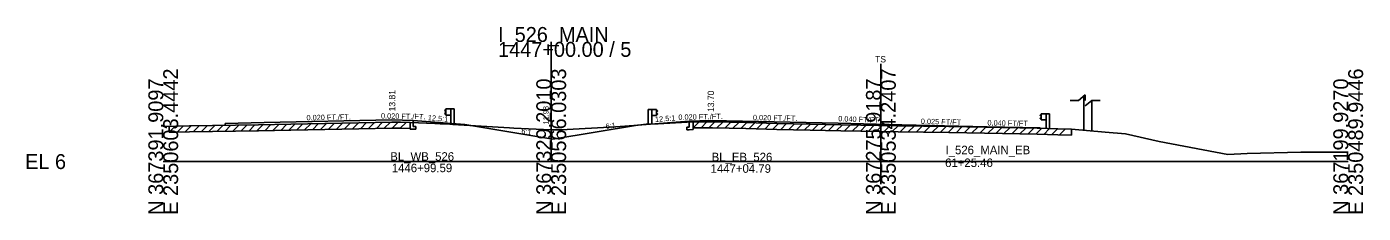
# Model space of a CAD drawing. Extents: x -170 to 2527928, y -10 to 1619750.
# Drawn here: x 4974.3 to 5225.9, y 7990.3 to 8025.3 of the extents above; entities that cross this region are included whole.
import ezdxf

# ---------------------------------------------------------------- set-up
doc = ezdxf.new("R2010")
doc.units = 0
for name, color, linetype in [('Default', 7, 'Continuous'), ('RD_GPK_XS_Cell', 7, 'Continuous'), ('RD_PD_NOISE-WALL-GM', 7, 'Continuous'), ('RD_XS_Base', 7, 'Continuous'), ('RD_XS_EarthShd', 7, 'Continuous'), ('RD_XS_ExGround', 7, 'Continuous'), ('RD_XS_ExPaveRet', 7, 'Continuous'), ('RD_XS_GR', 7, 'Continuous'), ('RD_XS_MatchLine', 7, 'Continuous'), ('RD_XS_Pave', 7, 'Continuous'), ('RD_XS_PaveShd', 7, 'Continuous'), ('RD_XS_TieSlope', 7, 'Continuous'), ('RD_XS_TX_Elev_EX', 7, 'Continuous'), ('RD_XS_TX_Slope', 7, 'Continuous'), ('RD_XS_TX_Station', 7, 'Continuous')]:
    doc.layers.add(name, color=color, linetype=linetype)

msp = doc.modelspace()

# ---------------------------------------------------------------- linework, layer by layer
at = {"layer": 'Default'}
for p, q in [((5173.53, 8012.52), (5172.28, 8011.5)), ((5173.53, 8011.5), (5173.53, 8012.52)), ((5172.28, 8011.5), (5170.7, 8011.5)), ((5174.78, 8011.5), (5173.53, 8010.47)), ((5176.37, 8011.5), (5174.78, 8011.5))]:
    msp.add_line(p, q, dxfattribs=at)
at = {"layer": 'RD_GPK_XS_Cell'}
for p, q in [((5073.02, 8000), (5073.02, 8022.47)), ((5000, 8000), (5073.02, 8000)), ((5073.02, 8000), (5135.07, 8000)), ((5135.07, 8000), (5223.03, 8000))]:
    msp.add_line(p, q, dxfattribs=at)
at = {"layer": 'RD_PD_NOISE-WALL-GM'}
for p, q in [((5173.27, 8005.89), (5173.27, 8012.31)), ((5174.77, 8005.75), (5174.77, 8011.5))]:
    msp.add_line(p, q, dxfattribs=at)
at = {"layer": 'RD_XS_Base'}
for p, q in [((5046.45, 8006.1), (5046.45, 8007.34)), ((5047.02, 8006.59), (5047.02, 8007.73)), ((5099.02, 8006.48), (5099.02, 8007.62)), ((5099.72, 8006), (5099.72, 8007.49)), ((5046.45, 8006.1), (5047.52, 8006.08)), ((5047.52, 8006.58), (5047.02, 8006.59)), ((5047.52, 8006.08), (5047.52, 8006.58)), ((5098.52, 8006.47), (5099.02, 8006.48)), ((5098.52, 8005.97), (5098.52, 8006.47)), ((5099.02, 8005.98), (5098.52, 8005.97)), ((5099.02, 8005.98), (5099.72, 8006)), ((5165.08, 8006.25), (5165.08, 8006.32))]:
    msp.add_line(p, q, dxfattribs=at)
at = {"layer": 'RD_XS_EarthShd'}
for p, q in [((5047.02, 8007.73), (5056.77, 8006.95)), ((5099.02, 8007.62), (5089.27, 8006.84))]:
    msp.add_line(p, q, dxfattribs=at)
at = {"layer": 'RD_XS_ExGround'}
msp.add_lwpolyline([(5000, 8006.59), (5002.37, 8006.66), (5004.93, 8006.7), (5017.94, 8006.89), (5024.04, 8007.03), (5030.44, 8007.17), (5036.84, 8007.3), (5043.05, 8007.41), (5044.65, 8007.38), (5046.45, 8007.34), (5051.12, 8007.18), (5051.81, 8007.15), (5052.14, 8007.11), (5052.55, 8007.1), (5053.36, 8007.07), (5054.52, 8006.98), (5065.18, 8006.33), (5065.96, 8006.28), (5072.94, 8005.99), (5073.87, 8005.94), (5074.88, 8005.99), (5085.13, 8006.5), (5085.16, 8006.5), (5089.39, 8006.87), (5090.89, 8007), (5093.14, 8007.12), (5099.72, 8007.49), (5100.47, 8007.48), (5103.41, 8007.47), (5109.66, 8007.32), (5115.52, 8007.18), (5121.75, 8007.04), (5127.53, 8006.92), (5135.07, 8006.79), (5138.31, 8006.74), (5147.86, 8006.57), (5157.96, 8006.38), (5164.47, 8006.27), (5168.37, 8006.17), (5170.92, 8006.1), (5177.31, 8005.52), (5181.09, 8005.22), (5187.42, 8003.78), (5200.37, 8001.35), (5204.01, 8001.49), (5214.1, 8001.79), (5223.03, 8001.75)], dxfattribs=at)
at = {"layer": 'RD_XS_ExPaveRet'}
for p, q in [((5028.11, 8005.99), (5029.25, 8007.14)), ((5029.61, 8006.03), (5030.75, 8007.17)), ((5031.11, 8006.06), (5032.25, 8007.2)), ((5032.61, 8006.09), (5033.75, 8007.24)), ((5034.11, 8006.12), (5035.25, 8007.27)), ((5035.61, 8006.15), (5036.75, 8007.3)), ((5037.11, 8006.18), (5038.25, 8007.32)), ((5038.61, 8006.21), (5039.75, 8007.35)), ((5040.11, 8006.24), (5041.25, 8007.38)), ((5041.61, 8006.26), (5042.75, 8007.41)), ((5043.11, 8006.29), (5044.2, 8007.39)), ((5044.61, 8006.26), (5045.7, 8007.36)), ((5046.45, 8007.34), (5046.45, 8006.22)), ((5099.72, 8006.37), (5099.72, 8007.49)), ((5099.72, 8006.37), (5100.84, 8007.48)), ((5101.22, 8006.36), (5102.34, 8007.47)), ((5102.72, 8006.35), (5103.83, 8007.46)), ((5104.22, 8006.33), (5105.32, 8007.42)), ((5105.72, 8006.29), (5106.82, 8007.39)), ((5107.22, 8006.26), (5108.32, 8007.35)), ((5108.72, 8006.22), (5109.82, 8007.32)), ((5110.22, 8006.18), (5111.32, 8007.28)), ((5111.72, 8006.15), (5112.82, 8007.24)), ((5113.22, 8006.11), (5114.32, 8007.21)), ((5114.72, 8006.07), (5115.82, 8007.17)), ((5116.22, 8006.04), (5117.32, 8007.14)), ((5001.11, 8005.5), (5002.26, 8006.65)), ((5001.11, 8005.5), (5001.11, 8006.62)), ((5001.11, 8005.5), (5002.37, 8005.53)), ((5002.37, 8005.53), (5004.93, 8005.57)), ((5002.61, 8005.54), (5003.74, 8006.68)), ((5004.11, 8005.56), (5005.24, 8006.7)), ((5004.93, 8005.57), (5017.94, 8005.76)), ((5005.61, 8005.58), (5006.74, 8006.72)), ((5007.11, 8005.61), (5008.24, 8006.74)), ((5008.61, 8005.63), (5009.74, 8006.77)), ((5010.11, 8005.65), (5011.24, 8006.79)), ((5011.61, 8005.67), (5012.74, 8006.81)), ((5013.11, 8005.69), (5014.24, 8006.83)), ((5014.61, 8005.72), (5015.74, 8006.85)), ((5016.11, 8005.74), (5017.24, 8006.88)), ((5017.61, 8005.76), (5018.75, 8006.9)), ((5017.94, 8005.76), (5024.04, 8005.9)), ((5019.11, 8005.79), (5020.25, 8006.94)), ((5020.61, 8005.83), (5021.75, 8006.97)), ((5022.11, 8005.86), (5023.25, 8007.01)), ((5023.61, 8005.89), (5024.75, 8007.04)), ((5024.04, 8005.9), (5030.44, 8006.05)), ((5025.11, 8005.93), (5026.25, 8007.07)), ((5026.61, 8005.96), (5027.75, 8007.11)), ((5030.44, 8006.05), (5036.84, 8006.18)), ((5036.84, 8006.18), (5043.05, 8006.29)), ((5043.05, 8006.29), (5044.65, 8006.26)), ((5044.65, 8006.26), (5046.45, 8006.22)), ((5099.72, 8006.37), (5100.47, 8006.36)), ((5100.47, 8006.36), (5103.41, 8006.35)), ((5103.41, 8006.35), (5109.66, 8006.2)), ((5109.66, 8006.2), (5115.52, 8006.05)), ((5115.52, 8006.05), (5121.75, 8005.92)), ((5117.72, 8006.01), (5118.82, 8007.1)), ((5119.22, 8005.97), (5120.32, 8007.07)), ((5120.72, 8005.94), (5121.82, 8007.04)), ((5121.75, 8005.92), (5127.53, 8005.8)), ((5122.22, 8005.91), (5123.32, 8007.01)), ((5123.72, 8005.88), (5124.82, 8006.98)), ((5125.22, 8005.85), (5126.32, 8006.95)), ((5126.72, 8005.82), (5127.82, 8006.92)), ((5127.53, 8005.8), (5135.07, 8005.67)), ((5128.22, 8005.79), (5129.33, 8006.89)), ((5129.72, 8005.76), (5130.83, 8006.87)), ((5131.22, 8005.74), (5132.33, 8006.84)), ((5132.72, 8005.71), (5133.83, 8006.81)), ((5134.22, 8005.69), (5135.33, 8006.79)), ((5135.07, 8005.67), (5138.31, 8005.61)), ((5135.72, 8005.66), (5136.83, 8006.76)), ((5137.22, 8005.63), (5138.33, 8006.74)), ((5138.31, 8005.61), (5147.86, 8005.44)), ((5138.72, 8005.61), (5139.83, 8006.71)), ((5140.22, 8005.58), (5141.33, 8006.68)), ((5141.72, 8005.55), (5142.83, 8006.65)), ((5143.22, 8005.53), (5144.33, 8006.63)), ((5144.72, 8005.5), (5145.83, 8006.6)), ((5146.22, 8005.47), (5147.33, 8006.57)), ((5147.72, 8005.45), (5148.82, 8006.55)), ((5147.86, 8005.44), (5157.96, 8005.26)), ((5149.22, 8005.42), (5150.32, 8006.52)), ((5150.72, 8005.39), (5151.82, 8006.49)), ((5152.22, 8005.37), (5153.32, 8006.47)), ((5153.72, 8005.34), (5154.82, 8006.44)), ((5155.22, 8005.31), (5156.32, 8006.41)), ((5156.72, 8005.28), (5157.82, 8006.39)), ((5157.96, 8005.26), (5164.47, 8005.14)), ((5158.22, 8005.26), (5159.33, 8006.36)), ((5159.72, 8005.23), (5160.83, 8006.33)), ((5161.22, 8005.2), (5162.33, 8006.3)), ((5162.72, 8005.18), (5163.83, 8006.28)), ((5164.22, 8005.15), (5165.32, 8006.24)), ((5164.47, 8005.14), (5168.37, 8005.05)), ((5165.72, 8005.11), (5166.82, 8006.21)), ((5167.22, 8005.08), (5168.32, 8006.17)), ((5168.37, 8005.05), (5170.92, 8004.98)), ((5168.72, 8005.04), (5169.82, 8006.13)), ((5170.92, 8006.1), (5170.92, 8004.98))]:
    msp.add_line(p, q, dxfattribs=at)
at = {"layer": 'RD_XS_GR'}
for p, q in [((5053.19, 8009.82), (5053.02, 8009.62)), ((5053.19, 8008.72), (5053.19, 8009.89)), ((5053.19, 8009.89), (5054.11, 8009.89)), ((5054.11, 8009.89), (5054.77, 8009.89)), ((5054.11, 8009.89), (5054.11, 8007.15)), ((5054.77, 8009.89), (5054.77, 8007.09)), ((5091.94, 8009.8), (5091.27, 8009.8)), ((5091.27, 8009.8), (5091.27, 8007)), ((5092.85, 8009.8), (5091.94, 8009.8)), ((5091.94, 8009.8), (5091.94, 8007.05)), ((5092.85, 8008.63), (5092.85, 8009.8)), ((5092.85, 8009.72), (5093.02, 8009.52)), ((5053.02, 8009.62), (5053.02, 8009.57)), ((5053.02, 8009.57), (5053.19, 8009.37)), ((5053.02, 8009.05), (5053.19, 8009.25)), ((5053.02, 8009), (5053.02, 8009.05)), ((5053.19, 8008.8), (5053.02, 8009)), ((5053.19, 8008.72), (5054.11, 8008.72)), ((5092.85, 8008.63), (5091.94, 8008.63)), ((5093.02, 8009.47), (5092.85, 8009.27)), ((5093.02, 8008.95), (5092.85, 8009.15)), ((5092.85, 8008.7), (5093.02, 8008.9)), ((5093.02, 8009.52), (5093.02, 8009.47)), ((5093.02, 8008.9), (5093.02, 8008.95)), ((5165.25, 8008.92), (5165.08, 8008.72)), ((5165.08, 8008.72), (5165.08, 8008.67)), ((5165.08, 8008.67), (5165.25, 8008.47)), ((5165.08, 8008.15), (5165.25, 8008.35)), ((5165.08, 8008.1), (5165.08, 8008.15)), ((5165.25, 8007.9), (5165.08, 8008.1)), ((5165.25, 8007.82), (5165.25, 8008.99)), ((5165.25, 8008.99), (5166.17, 8008.99)), ((5165.25, 8007.82), (5166.17, 8007.82)), ((5166.17, 8008.99), (5166.83, 8008.99)), ((5166.17, 8008.99), (5166.17, 8006.25)), ((5166.83, 8008.99), (5166.83, 8006.19))]:
    msp.add_line(p, q, dxfattribs=at)
at = {"layer": 'RD_XS_MatchLine'}
msp.add_line((5135.07, 7995.76), (5135.07, 8018.35), dxfattribs=at)
at = {"layer": 'RD_XS_Pave'}
for p, q in [((5011.66, 8007.18), (5019.02, 8007.33)), ((5019.02, 8007.33), (5043.02, 8007.81)), ((5103.02, 8007.7), (5127.02, 8007.22)), ((5139.04, 8006.91), (5155.07, 8006.51))]:
    msp.add_line(p, q, dxfattribs=at)
at = {"layer": 'RD_XS_PaveShd'}
for p, q in [((5011.66, 8006.79), (5011.66, 8007.18)), ((5043.02, 8007.81), (5047.02, 8007.73)), ((5099.02, 8007.62), (5103.02, 8007.7)), ((5127.02, 8007.22), (5139.04, 8006.91)), ((5155.07, 8006.51), (5165.08, 8006.32))]:
    msp.add_line(p, q, dxfattribs=at)
at = {"layer": 'RD_XS_TieSlope'}
for p in [(5056.77, 8006.95), (5089.27, 8006.84)]:
    msp.add_line(p, (5073.35, 8004.19), dxfattribs=at)

# ---------------------------------------------------------------- texts
at = {"layer": 'RD_GPK_XS_Cell'}
for s, p in [('I_526_MAIN', (5063.02, 8022.47)), ('1447+00.00 / 5', (5063.02, 8019.67)), ('EL 6', (4974, 7998.6))]:
    msp.add_text(s, height=2.8, dxfattribs=at).set_placement(p)
for s, p in [('E 2350603.4442', (5002.8, 7990)), ('E 2350566.0303', (5075.82, 7990)), ('E 2350534.2407', (5137.87, 7990)), ('E 2350489.9446', (5225.83, 7990)), ('N 367391.9097', (5000, 7990)), ('N 367329.2010', (5073.02, 7990)), ('N 367275.9187', (5135.07, 7990)), ('N 367199.9270', (5223.03, 7990))]:
    msp.add_text(s, height=2.8, rotation=90, dxfattribs=at).set_placement(p)
at = {"layer": 'RD_XS_MatchLine'}
msp.add_text('TS', height=1.2, dxfattribs=at).set_placement((5133.99, 8018.62))
at = {"layer": 'RD_XS_TX_Elev_EX'}
msp.add_text('11.98', height=1, rotation=90, dxfattribs=at).set_placement((5072.52, 8006.98))
at = {"layer": 'RD_XS_TX_Slope'}
for s, rotation, p in [('0.020 FT./FT.', 1.1458, (5026.97, 8007.74)), ('0.020 FT./FT.', 358.8542, (5040.98, 8008.1)), ('12.5:1', 355.4261, (5049.78, 8007.77)), ('6:1', 9.4623, (5083.35, 8006.09)), ('12.5:1', 4.5739, (5092.6, 8007.42)), ('0.020 FT./FT.', 1.1458, (5096.97, 8007.83)), ('0.020 FT./FT.', 358.8542, (5110.98, 8007.79)), ('0.040 FT/FT', 357.7094, (5127.03, 8007.58)), ('0.025 FT/FT', 358.5427, (5142.58, 8007.08)), ('0.040 FT/FT', 359.1102, (5155.12, 8006.78)), ('6:1', 350.5446, (5067.35, 8005.27))]:
    msp.add_text(s, height=1, rotation=rotation, dxfattribs=at).set_placement(p)
at = {"layer": 'RD_XS_TX_Station'}
for s, p in [(' 13.81', (5043.68, 8008.98)), (' 13.70', (5103.68, 8008.87))]:
    msp.add_text(s, height=1.2, rotation=90, dxfattribs=at).set_placement(p)
for s, p in [('I_526_MAIN_EB', (5147.24, 8001.38)), ('BL_WB_526', (5042.73, 8000.16)), ('1446+99.59', (5043.02, 7998.01)), ('BL_EB_526', (5103.22, 8000.06)), ('61+25.46', (5147.16, 7998.98)), ('1447+04.79', (5103.02, 7997.9))]:
    msp.add_text(s, height=1.6, dxfattribs=at).set_placement(p)

doc.saveas('drawing.dxf')
